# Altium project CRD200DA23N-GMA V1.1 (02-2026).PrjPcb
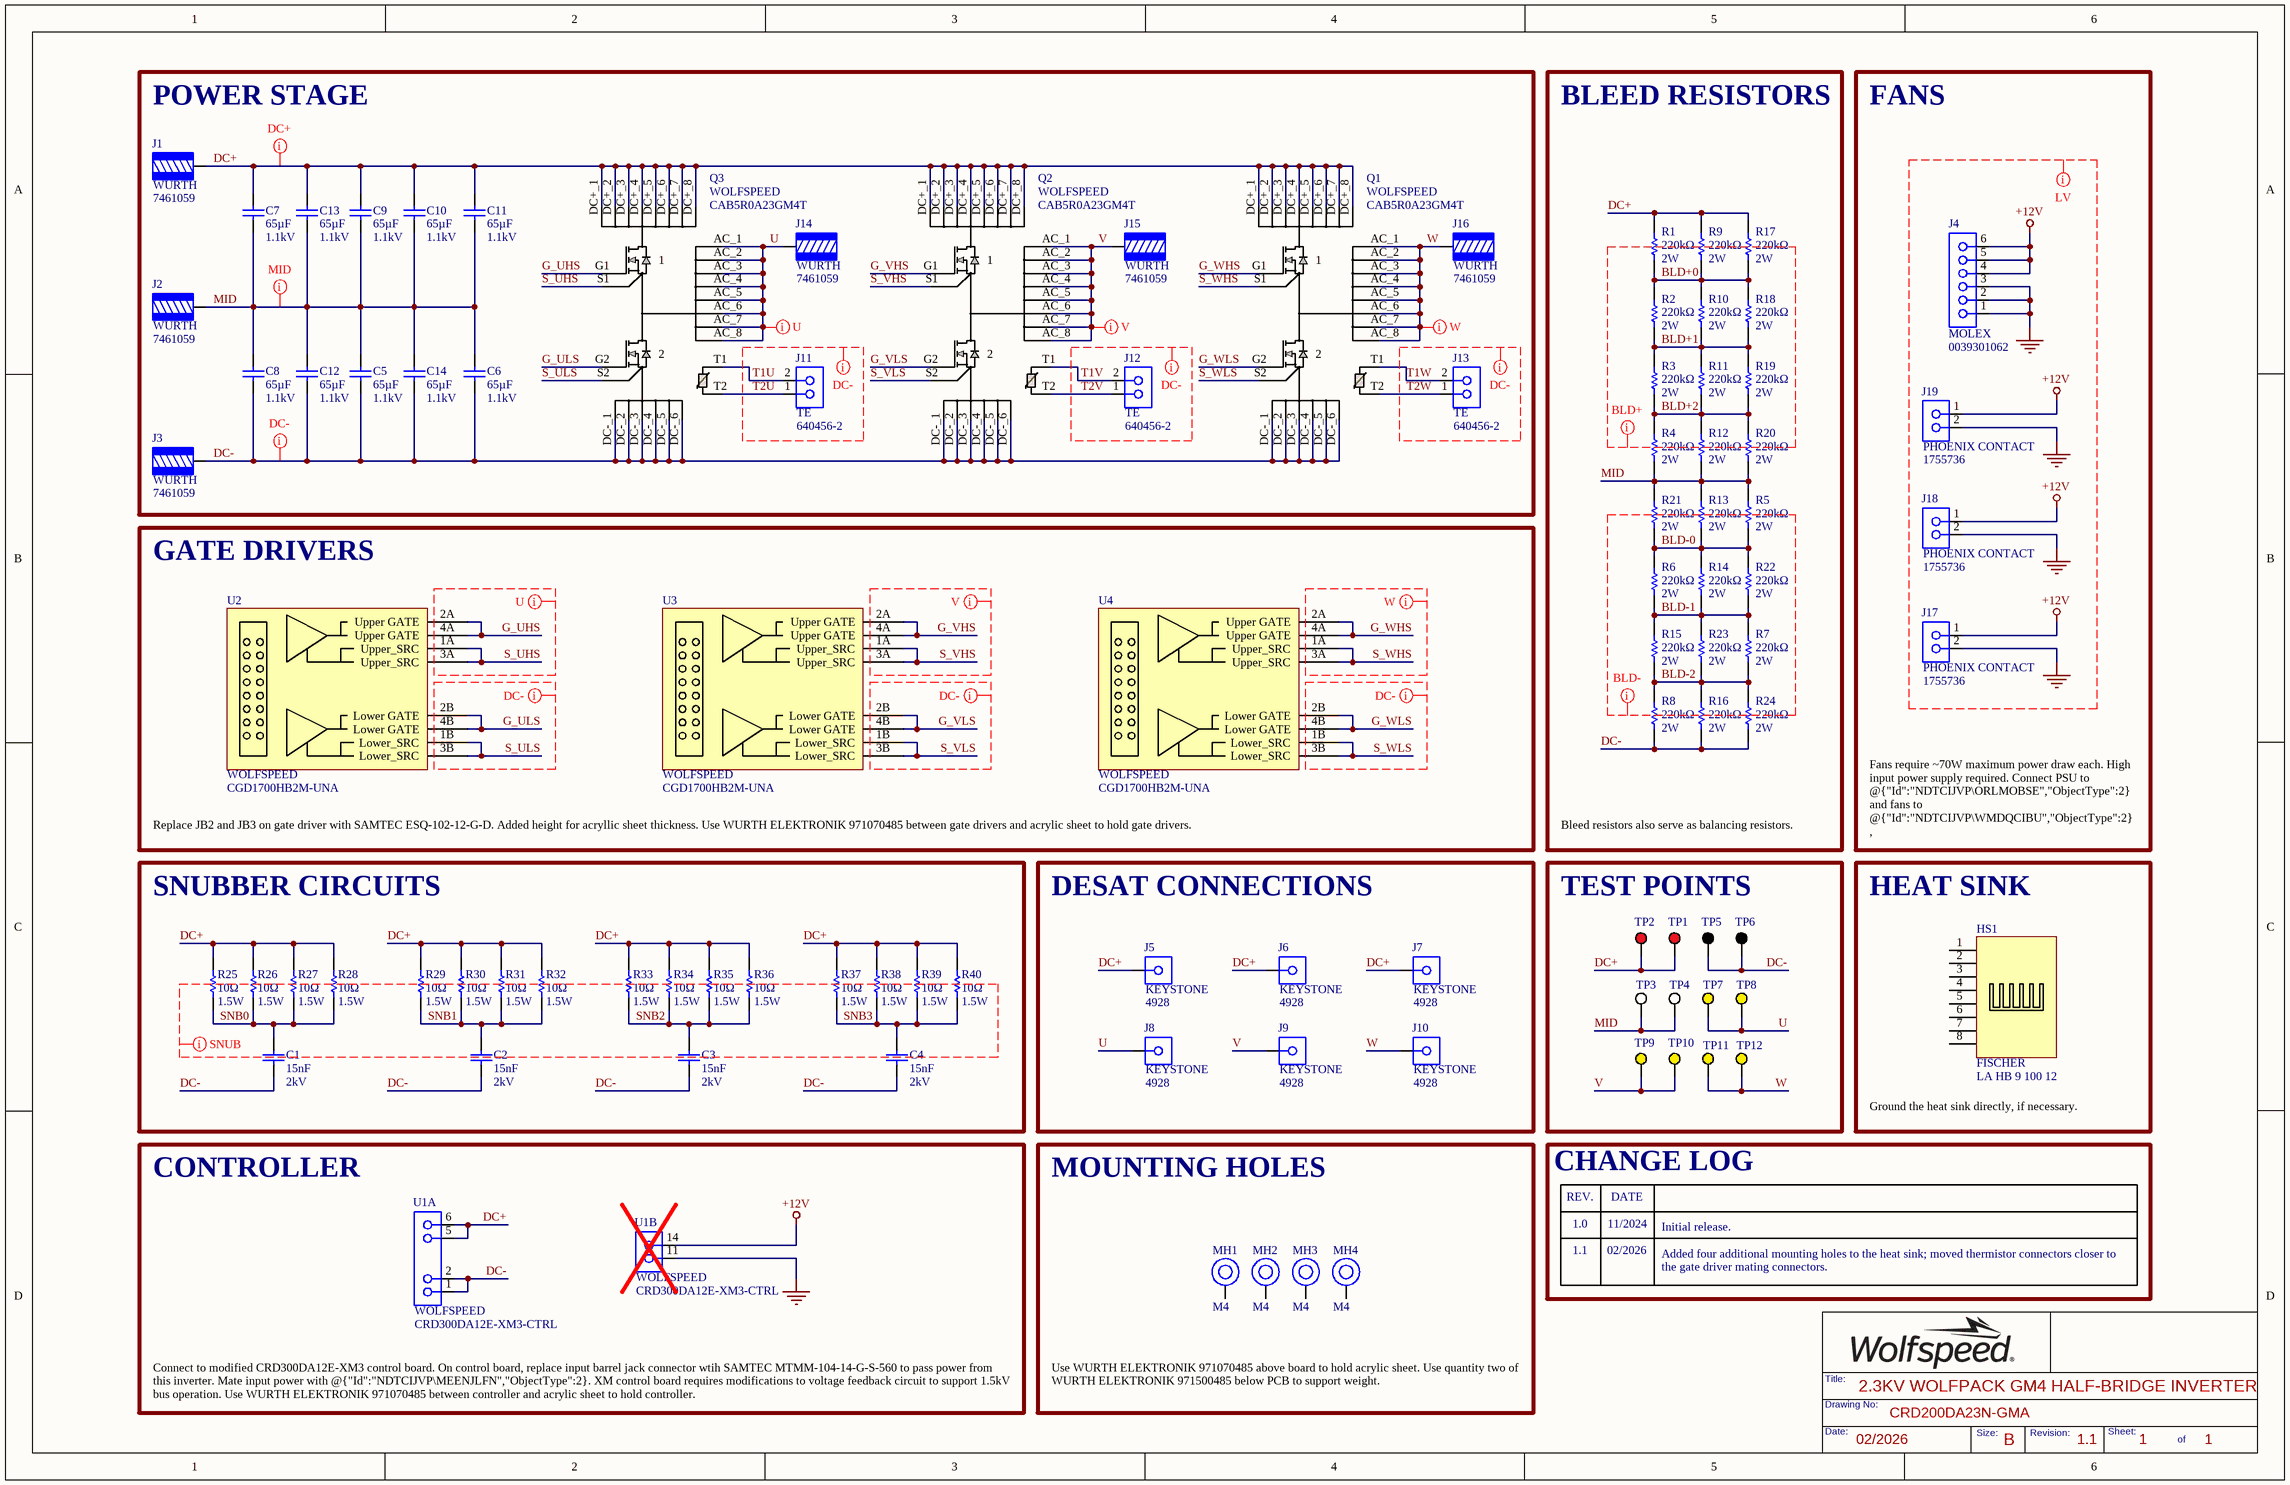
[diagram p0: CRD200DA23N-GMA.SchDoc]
1 sheet, 97 parts. Net scope: global (net labels, ports and power ports of the same name join across sheets).
Board file: CRD200DA23N-GMA V1.1 (02-2026).PcbDoc

## Sheet CRD200DA23N-GMA.SchDoc: 2.3KV WOLFPACK GM4 HALF-BRIDGE INVERTER
size 431 x 279 mm; Date: 02/2026; DocumentNumber: CRD200DA23N-GMA; Revision: 1.1; SheetNumber: 1; SheetTotal: 1; SheetSize: B

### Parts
C1  value 15nF  Voltage: 2kV  [CAPC9501060_270N_KEM]  (hidden comment: C3640C153JGGACAUTO)
C2  value 15nF  Voltage: 2kV  [CAPC9501060_270N_KEM]  (hidden comment: C3640C153JGGACAUTO)
C3  value 15nF  Voltage: 2kV  [CAPC9501060_270N_KEM]  (hidden comment: C3640C153JGGACAUTO)
C4  value 15nF  Voltage: 2kV  [CAPC9501060_270N_KEM]  (hidden comment: C3640C153JGGACAUTO)
C5  value 65µF  Voltage: 1.1kV  [C4AQNEW5650M3BJ]  (hidden comment: C4AQQEW5650A3BJ)
C6  value 65µF  Voltage: 1.1kV  [C4AQNEW5650M3BJ]  (hidden comment: C4AQQEW5650A3BJ)
C7  value 65µF  Voltage: 1.1kV  [C4AQNEW5650M3BJ]  (hidden comment: C4AQQEW5650A3BJ)
C8  value 65µF  Voltage: 1.1kV  [C4AQNEW5650M3BJ]  (hidden comment: C4AQQEW5650A3BJ)
C9  value 65µF  Voltage: 1.1kV  [C4AQNEW5650M3BJ]  (hidden comment: C4AQQEW5650A3BJ)
C10  value 65µF  Voltage: 1.1kV  [C4AQNEW5650M3BJ]  (hidden comment: C4AQQEW5650A3BJ)
C11  value 65µF  Voltage: 1.1kV  [C4AQNEW5650M3BJ]  (hidden comment: C4AQQEW5650A3BJ)
C12  value 65µF  Voltage: 1.1kV  [C4AQNEW5650M3BJ]  (hidden comment: C4AQQEW5650A3BJ)
C13  value 65µF  Voltage: 1.1kV  [C4AQNEW5650M3BJ]  (hidden comment: C4AQQEW5650A3BJ)
C14  value 65µF  Voltage: 1.1kV  [C4AQNEW5650M3BJ]  (hidden comment: C4AQQEW5650A3BJ)
HS1  Manufacturer: FISCHER  [LA HB 9 100]  (hidden comment: LA HB 9 100 12)
J1  Manufacturer: WURTH  [7461059]  (hidden comment: 7461059)
J2  Manufacturer: WURTH  [7461059]  (hidden comment: 7461059)
J3  Manufacturer: WURTH  [7461059]  (hidden comment: 7461059)
J4  Manufacturer: MOLEX  [FP-39-30-1062-MFG]  (hidden comment: 0039301062)
J5  Manufacturer: KEYSTONE  [KEYSTONE_4928]  (hidden comment: 4928)
J6  Manufacturer: KEYSTONE  [KEYSTONE_4928]  (hidden comment: 4928)
J7  Manufacturer: KEYSTONE  [KEYSTONE_4928]  (hidden comment: 4928)
J8  Manufacturer: KEYSTONE  [KEYSTONE_4928]  (hidden comment: 4928)
J9  Manufacturer: KEYSTONE  [KEYSTONE_4928]  (hidden comment: 4928)
J10  Manufacturer: KEYSTONE  [KEYSTONE_4928]  (hidden comment: 4928)
J11  640456-2  Manufacturer Print: TE  [TECO-640456-2_V]
J12  640456-2  Manufacturer Print: TE  [TECO-640456-2_V]
J13  640456-2  Manufacturer Print: TE  [TECO-640456-2_V]
J14  Manufacturer: WURTH  [7461059]  (hidden comment: 7461059)
J15  Manufacturer: WURTH  [7461059]  (hidden comment: 7461059)
J16  Manufacturer: WURTH  [7461059]  (hidden comment: 7461059)
J17  1755736  Manufacturer: PHOENIX CONTACT  [1755736]
J18  1755736  Manufacturer: PHOENIX CONTACT  [1755736]
J19  1755736  Manufacturer: PHOENIX CONTACT  [1755736]
MH1  Size: M4  [MH_M4_P]  (hidden comment: MH_M4_P)
MH2  Size: M4  [MH_M4_P]  (hidden comment: MH_M4_P)
MH3  Size: M4  [MH_M4_P]  (hidden comment: MH_M4_P)
MH4  Size: M4  [MH_M4_P]  (hidden comment: MH_M4_P)
Q1  Manufacturer: WOLFSPEED  [CAB5R0A23GM4_NOHOLE]  (hidden comment: CAB5R0A23GM4T)
Q2  Manufacturer: WOLFSPEED  [CAB5R0A23GM4_NOHOLE]  (hidden comment: CAB5R0A23GM4T)
Q3  Manufacturer: WOLFSPEED  [CAB5R0A23GM4_NOHOLE]  (hidden comment: CAB5R0A23GM4T)
R1  Resistance: 220kΩ  Power Rating: 2W  [FP-CRGP2512-IPC_C]  (hidden comment: CRGP2512F220K)
R2  Resistance: 220kΩ  Power Rating: 2W  [FP-CRGP2512-IPC_C]  (hidden comment: CRGP2512F220K)
R3  Resistance: 220kΩ  Power Rating: 2W  [FP-CRGP2512-IPC_C]  (hidden comment: CRGP2512F220K)
R4  Resistance: 220kΩ  Power Rating: 2W  [FP-CRGP2512-IPC_C]  (hidden comment: CRGP2512F220K)
R5  Resistance: 220kΩ  Power Rating: 2W  [FP-CRGP2512-IPC_C]  (hidden comment: CRGP2512F220K)
R6  Resistance: 220kΩ  Power Rating: 2W  [FP-CRGP2512-IPC_C]  (hidden comment: CRGP2512F220K)
R7  Resistance: 220kΩ  Power Rating: 2W  [FP-CRGP2512-IPC_C]  (hidden comment: CRGP2512F220K)
R8  Resistance: 220kΩ  Power Rating: 2W  [FP-CRGP2512-IPC_C]  (hidden comment: CRGP2512F220K)
R9  Resistance: 220kΩ  Power Rating: 2W  [FP-CRGP2512-IPC_C]  (hidden comment: CRGP2512F220K)
R10  Resistance: 220kΩ  Power Rating: 2W  [FP-CRGP2512-IPC_C]  (hidden comment: CRGP2512F220K)
R11  Resistance: 220kΩ  Power Rating: 2W  [FP-CRGP2512-IPC_C]  (hidden comment: CRGP2512F220K)
R12  Resistance: 220kΩ  Power Rating: 2W  [FP-CRGP2512-IPC_C]  (hidden comment: CRGP2512F220K)
R13  Resistance: 220kΩ  Power Rating: 2W  [FP-CRGP2512-IPC_C]  (hidden comment: CRGP2512F220K)
R14  Resistance: 220kΩ  Power Rating: 2W  [FP-CRGP2512-IPC_C]  (hidden comment: CRGP2512F220K)
R15  Resistance: 220kΩ  Power Rating: 2W  [FP-CRGP2512-IPC_C]  (hidden comment: CRGP2512F220K)
R16  Resistance: 220kΩ  Power Rating: 2W  [FP-CRGP2512-IPC_C]  (hidden comment: CRGP2512F220K)
R17  Resistance: 220kΩ  Power Rating: 2W  [FP-CRGP2512-IPC_C]  (hidden comment: CRGP2512F220K)
R18  Resistance: 220kΩ  Power Rating: 2W  [FP-CRGP2512-IPC_C]  (hidden comment: CRGP2512F220K)
R19  Resistance: 220kΩ  Power Rating: 2W  [FP-CRGP2512-IPC_C]  (hidden comment: CRGP2512F220K)
R20  Resistance: 220kΩ  Power Rating: 2W  [FP-CRGP2512-IPC_C]  (hidden comment: CRGP2512F220K)
R21  Resistance: 220kΩ  Power Rating: 2W  [FP-CRGP2512-IPC_C]  (hidden comment: CRGP2512F220K)
R22  Resistance: 220kΩ  Power Rating: 2W  [FP-CRGP2512-IPC_C]  (hidden comment: CRGP2512F220K)
R23  Resistance: 220kΩ  Power Rating: 2W  [FP-CRGP2512-IPC_C]  (hidden comment: CRGP2512F220K)
R24  Resistance: 220kΩ  Power Rating: 2W  [FP-CRGP2512-IPC_C]  (hidden comment: CRGP2512F220K)
R25  value 10Ω  Power: 1.5W  [FP-RMCF2512-IPC_A]  (hidden comment: CRCW251210R0FKEGHP)
R26  value 10Ω  Power: 1.5W  [FP-RMCF2512-IPC_A]  (hidden comment: CRCW251210R0FKEGHP)
R27  value 10Ω  Power: 1.5W  [FP-RMCF2512-IPC_A]  (hidden comment: CRCW251210R0FKEGHP)
R28  value 10Ω  Power: 1.5W  [FP-RMCF2512-IPC_A]  (hidden comment: CRCW251210R0FKEGHP)
R29  value 10Ω  Power: 1.5W  [FP-RMCF2512-IPC_A]  (hidden comment: CRCW251210R0FKEGHP)
R30  value 10Ω  Power: 1.5W  [FP-RMCF2512-IPC_A]  (hidden comment: CRCW251210R0FKEGHP)
R31  value 10Ω  Power: 1.5W  [FP-RMCF2512-IPC_A]  (hidden comment: CRCW251210R0FKEGHP)
R32  value 10Ω  Power: 1.5W  [FP-RMCF2512-IPC_A]  (hidden comment: CRCW251210R0FKEGHP)
R33  value 10Ω  Power: 1.5W  [FP-RMCF2512-IPC_A]  (hidden comment: CRCW251210R0FKEGHP)
R34  value 10Ω  Power: 1.5W  [FP-RMCF2512-IPC_A]  (hidden comment: CRCW251210R0FKEGHP)
R35  value 10Ω  Power: 1.5W  [FP-RMCF2512-IPC_A]  (hidden comment: CRCW251210R0FKEGHP)
R36  value 10Ω  Power: 1.5W  [FP-RMCF2512-IPC_A]  (hidden comment: CRCW251210R0FKEGHP)
R37  value 10Ω  Power: 1.5W  [FP-RMCF2512-IPC_A]  (hidden comment: CRCW251210R0FKEGHP)
R38  value 10Ω  Power: 1.5W  [FP-RMCF2512-IPC_A]  (hidden comment: CRCW251210R0FKEGHP)
R39  value 10Ω  Power: 1.5W  [FP-RMCF2512-IPC_A]  (hidden comment: CRCW251210R0FKEGHP)
R40  value 10Ω  Power: 1.5W  [FP-RMCF2512-IPC_A]  (hidden comment: CRCW251210R0FKEGHP)
TP1  5010  [KSTN-5010_V]  (value not drawn)
TP2  5010  [KSTN-5010_V]  (value not drawn)
TP3  5012  [KSTN-5012_V]  (value not drawn)
TP4  5012  [KSTN-5012_V]  (value not drawn)
TP5  5011  [KSTN-5011_V]  (value not drawn)
TP6  5011  [KSTN-5011_V]  (value not drawn)
TP7  5014  [KSTN-5014_V]  (value not drawn)
TP8  5014  [KSTN-5014_V]  (value not drawn)
TP9  5014  [KSTN-5014_V]  (value not drawn)
TP10  5014  [KSTN-5014_V]  (value not drawn)
TP11  5014  [KSTN-5014_V]  (value not drawn)
TP12  5014  [KSTN-5014_V]  (value not drawn)
U1  Manufacturer: WOLFSPEED  Manufacturer Part Number: CRD300DA12E-XM3-CTRL  [XM CONTROLLER]  (hidden comment: XM Controller)  (parts A,B of 2)
U2  CGD1700HB2M-UNA  Manufacturer: WOLFSPEED  [CGD1700HB2P-UNA_NOHOLE]
U3  CGD1700HB2M-UNA  Manufacturer: WOLFSPEED  [CGD1700HB2P-UNA_NOHOLE]
U4  CGD1700HB2M-UNA  Manufacturer: WOLFSPEED  [CGD1700HB2P-UNA_NOHOLE]

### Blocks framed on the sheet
POWER STAGE: C5-C14 J1-J3 J11-J16 Q1-Q3
BLEED RESISTORS: R1-R24
FANS: J4 J17-J19
GATE DRIVERS: U2-U4
SNUBBER CIRCUITS: C1-C4 R25-R40
DESAT CONNECTIONS: J5-J10
TEST POINTS: TP1-TP12
HEAT SINK: HS1
CONTROLLER: U1
MOUNTING HOLES: MH1-MH4

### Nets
+12V: J4.4 J4.5 J4.6 J17.1 J18.1 J19.1 U1.14
GND: J4.1 J4.2 J4.3 J17.2 J18.2 J19.2 U1.11
BLD+0: R1.1 R2.2 R9.1 R10.2 R17.1 R18.2
BLD+1: R2.1 R3.2 R10.1 R11.2 R18.1 R19.2
BLD+2: R3.1 R4.2 R11.1 R12.2 R19.1 R20.2
BLD-0: R5.1 R6.2 R13.1 R14.2 R21.1 R22.2
BLD-1: R6.1 R7.2 R14.1 R15.2 R22.1 R23.2
BLD-2: R7.1 R8.2 R15.1 R16.2 R23.1 R24.2
DC+: C7.1A,1B C9.1A,1B C10.1A,1B C11.1A,1B C13.1A,1B J1.1 J5.1,2,3 J6.1,2,3 J7.1,2,3 Q1.DC+_1 Q1.DC+_2 Q1.DC+_3 Q1.DC+_4 Q1.DC+_5 Q1.DC+_6 Q1.DC+_7 Q1.DC+_8 Q2.DC+_1 Q2.DC+_2 Q2.DC+_3 Q2.DC+_4 Q2.DC+_5 Q2.DC+_6 Q2.DC+_7 Q2.DC+_8 Q3.DC+_1 Q3.DC+_2 Q3.DC+_3 Q3.DC+_4 Q3.DC+_5 Q3.DC+_6 Q3.DC+_7 Q3.DC+_8 R1.2 R9.2 R17.2 R25.2 R26.2 R27.2 R28.2 R29.2 R30.2 R31.2 R32.2 R33.2 R34.2 R35.2 R36.2 R37.2 R38.2 R39.2 R40.2 TP1.1 TP2.1 U1.5 U1.6
DC-: C1.2 C2.2 C3.2 C4.2 C5.2A,2B C6.2A,2B C8.2A,2B C12.2A,2B C14.2A,2B J3.1 Q1.DC-_1 Q1.DC-_2 Q1.DC-_3 Q1.DC-_4 Q1.DC-_5 Q1.DC-_6 Q2.DC-_1 Q2.DC-_2 Q2.DC-_3 Q2.DC-_4 Q2.DC-_5 Q2.DC-_6 Q3.DC-_1 Q3.DC-_2 Q3.DC-_3 Q3.DC-_4 Q3.DC-_5 Q3.DC-_6 R8.1 R16.1 R24.1 TP5.1 TP6.1 U1.1 U1.2
G_UHS: Q3.G1 U2.2A(Upper_GATE) U2.4A(Upper_GATE)
G_ULS: Q3.G2 U2.2B(Lower_GATE) U2.4B(Lower_GATE)
G_VHS: Q2.G1 U3.2A(Upper_GATE) U3.4A(Upper_GATE)
G_VLS: Q2.G2 U3.2B(Lower_GATE) U3.4B(Lower_GATE)
G_WHS: Q1.G1 U4.2A(Upper_GATE) U4.4A(Upper_GATE)
G_WLS: Q1.G2 U4.2B(Lower_GATE) U4.4B(Lower_GATE)
MID: C5.1A,1B C6.1A,1B C7.2A,2B C8.1A,1B C9.2A,2B C10.2A,2B C11.2A,2B C12.1A,1B C13.2A,2B C14.1A,1B J2.1 R4.1 R5.2 R12.1 R13.2 R20.1 R21.2 TP3.1 TP4.1
S_UHS: Q3.S1 U2.1A(Upper_SRC) U2.3A(Upper_SRC)
S_ULS: Q3.S2 U2.1B(Lower_SRC) U2.3B(Lower_SRC)
S_VHS: Q2.S1 U3.1A(Upper_SRC) U3.3A(Upper_SRC)
S_VLS: Q2.S2 U3.1B(Lower_SRC) U3.3B(Lower_SRC)
S_WHS: Q1.S1 U4.1A(Upper_SRC) U4.3A(Upper_SRC)
S_WLS: Q1.S2 U4.1B(Lower_SRC) U4.3B(Lower_SRC)
SNB0: C1.1 R25.1 R26.1 R27.1 R28.1
SNB1: C2.1 R29.1 R30.1 R31.1 R32.1
SNB2: C3.1 R33.1 R34.1 R35.1 R36.1
SNB3: C4.1 R37.1 R38.1 R39.1 R40.1
T1U: J11.2 Q3.T1(NTC1)
T1V: J12.2 Q2.T1(NTC1)
T1W: J13.2 Q1.T1(NTC1)
T2U: J11.1 Q3.T2
T2V: J12.1 Q2.T2
T2W: J13.1 Q1.T2
U: J8.1,2,3 J14.1 Q3.AC_1 Q3.AC_2 Q3.AC_3 Q3.AC_4 Q3.AC_5 Q3.AC_6 Q3.AC_7 Q3.AC_8 TP7.1 TP8.1
V: J9.1,2,3 J15.1 Q2.AC_1 Q2.AC_2 Q2.AC_3 Q2.AC_4 Q2.AC_5 Q2.AC_6 Q2.AC_7 Q2.AC_8 TP9.1 TP10.1
W: J10.1,2,3 J16.1 Q1.AC_1 Q1.AC_2 Q1.AC_3 Q1.AC_4 Q1.AC_5 Q1.AC_6 Q1.AC_7 Q1.AC_8 TP11.1 TP12.1

Not connected (* = marked no-connect by the designer): HS1 1 2 3 4 5 6 7 8; MH1 1; MH2 1; MH3 1; MH4 1

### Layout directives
net class DC+_CLASS: DC+
net class DC-_CLASS: DC-, G_ULS, G_VLS, G_WLS, S_ULS, S_VLS, S_WLS, T1U, T1V, T1W, T2U, T2V, T2W
net class MID_CLASS: MID
net class U_CLASS: G_UHS, S_UHS, U
net class V_CLASS: G_VHS, S_VHS, V
net class W_CLASS: G_WHS, S_WHS, W
net class LV_CLASS: +12V, GND
net class SNUB_CLASS: SNB0, SNB1, SNB2, SNB3
net class BLD+_CLASS: BLD+0, BLD+1, BLD+2
net class BLD-_CLASS: BLD-0, BLD-1, BLD-2

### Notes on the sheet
- Replace JB2 and JB3 on gate driver with SAMTEC ESQ-102-12-G-D. Added height for acryllic sheet thickness. Use WURTH ELEKTRONIK 971070485 between gate drivers and acrylic sheet to hold gate drivers.
- Bleed resistors also serve as balancing resistors.
- Fans require ~70W maximum power draw each. High input power supply required. Connect PSU to @{"Id":"NDTCIJVP\ORLMOBSE","ObjectType":2} and fans to @{"Id":"NDTCIJVP\WMDQCIBU","ObjectType":2} , @{"Id":"NDTCIJVP\XUWUPMDE","ObjectType":2}, and @{"Id":"NDTCIJVP\OCFQOGKO","ObjectType":2}. Recommended power supply CUI SDI300G-12-U-P219 or similar. Mating fan connector: PHOENIX CONTACT 1754449.
- Ground the heat sink directly, if necessary.
- CHANGE LOG
- 1.0
- REV.
- DATE
- 11/2024
- Initial release.
- 1.1
- 02/2026
- Added four additional mounting holes to the heat sink; moved thermistor connectors closer to the gate driver mating connectors.
- Connect to modified CRD300DA12E-XM3 control board. On control board, replace input barrel jack connector wtih SAMTEC MTMM-104-14-G-S-560 to pass power from this inverter. Mate input power with @{"Id":"NDTCIJVP\MEENJLFN","ObjectType":2}. XM control board requires modifications to voltage feedback circuit to support 1.5kV bus operation. Use WURTH ELEKTRONIK 971070485 between controller and acrylic sheet to hold controller.
- Use WURTH ELEKTRONIK 971070485 above board to hold acrylic sheet. Use quantity two of WURTH ELEKTRONIK 971500485 below PCB to support weight.

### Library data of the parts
C1-C4 = C3640C153JGGACAUTO: CAP CER 0.015UF 2KV C0G/NP0 3640; Manufacturer: KEMET
C5-C14 = C4AQQEW5650A3BJ: CAP FILM 65UF 5% 1.1KVDC RAD; Manufacturer: KEMET
HS1 = LA HB 9 100 12: HEATSINK EXTRUSION 100MM
J1-J3 J14-J16 = 7461059: TERM REDCUBE M6 16PIN PCB; NexarPartId: 75500417; Current Rating: 240A
J4 = 0039301062: CONN HEADER R/A 6POS 4.2MM
J5-J10 = 4928: QUICK FIT TERMINAL .240"
J11-J13 = CMP-2000-05417-1: CONN HEADER VERT 2POS 2.54MM; Standards: RoHSCompliant,ELVCompliant,UL94V-0; Material, Housing: Polyester; Agency Approvals: CSA,UL; Brand/Series: MTA-100Series; Contact Centerline Spacing: 0.100 / in.; Material, Contact: CopperAlloy; Current, Rating: 5 / A; Color, Housing: White; Contact Termination Area Plating: Tin; Special Features: Pinstrip; Number of Positions: 2; Pin Spacing: 0.1 / "; Temperature, Operating: -55to+105 / degC; Angle: Straight; Mount Angle: Vertical; Connector Type: MTA-100; Primary Type: InterconnectSystem; Voltage, Rating: 250 / V; Mounting Hole Size: 0.04 / "
J17-J19 = 1755736: TERM BLOCK HDR 2POS VERT 5.08MM; Content: 250pc(s); Industrial packaging: Yes; Number of contacts: 2
MH1-MH4 = MH_M4_P: PLASTIC SPACER STUD METRIC THREA; Manufacturer: WURTH; Manufacturer Part Number: 971500485
Q1-Q3 = CAB5R0A23GM4T: MOSFET 2N-CH 2300V 200A
R1-R24 = CRGP2512F220K: RES 220K OHM 1% 2W 2512; Manufacturer: TE; Value: 220kΩ; Temperature Coefficient: ±100ppm/°C; Tolerance: 0.01; Voltage Rating: 500V
R25-R40 = CRCW251210R0FKEGHP: RES SMD 10 OHM 1% 1.5W 2512; Manufacturer: VISHAY DALE
TP1 TP2 = CMP-1672-00002-4: PC TEST POINT MULTIPURPOSE RED; Manufacturer: KEYSTONE
TP3 TP4 = CMP-1672-00004-4: PC TEST POINT MULTIPURPOSE WHITE; Manufacturer: KEYSTONE
TP5 TP6 = CMP-1672-00003-4: PC TEST POINT MULTIPURPOSE BLACK; Manufacturer: KEYSTONE
TP7-TP12 = CMP-1672-00006-4: PC TEST POINT MULTIPURPOSE YELLOW; Manufacturer: KEYSTONE
U1 = XM Controller: CTRL BRD - XM3 EVAL BRD
U2-U4 = CGD1700HB2M-UNA: IC GATE DRVR HALF-BRIDGE MODULE; Sub-part1: TSM-102-02-S-DV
